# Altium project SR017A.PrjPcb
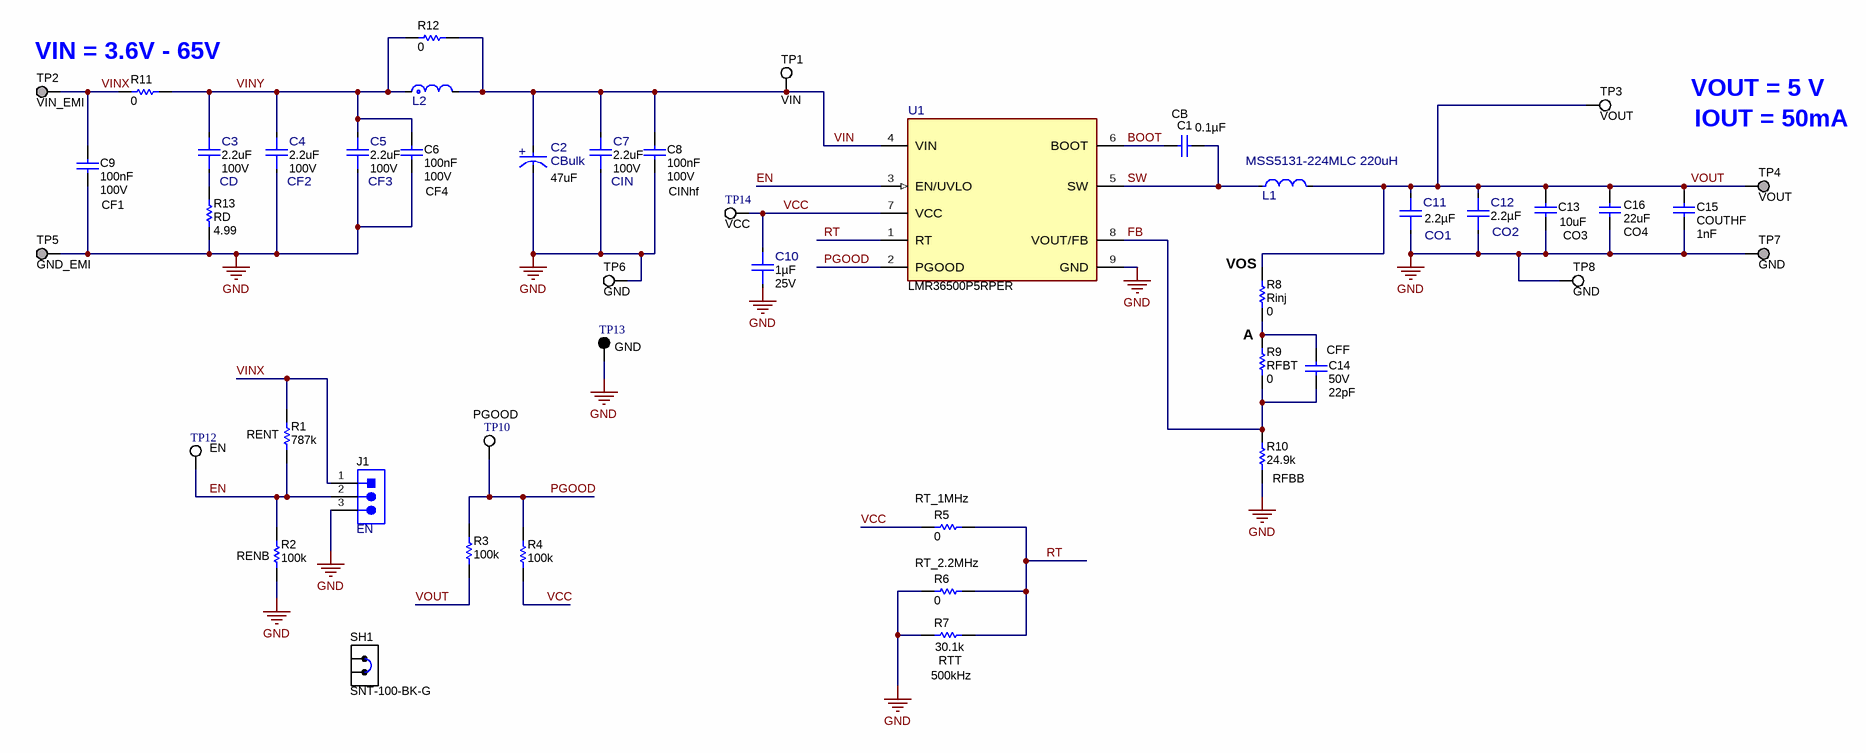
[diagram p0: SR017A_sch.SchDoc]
CopyrightYear: 2023; EVM_orderable: LMR36500EVM; PCB_Layout: FJD; PCB_Rev: A1; PRJ_Customer: Public Release; PRJ_Engineer: FJD; PRJ_Number: SR017; PRJ_Title: LMR36500EVM; SCH_Rev: A; TechSupport: http://www.ti.com/support; TID: N/A
2 sheets, 53 parts. Net scope: global (net labels, ports and power ports of the same name join across sheets).
Board file: SR017A_PCB.PcbDoc
Sheets:
  SR017A_sch.SchDoc
  SR017A_Hardware.SchDoc

## Sheet SR017A_sch.SchDoc
size 431 x 279 mm; Date: Not shown in title block; ApprovedBy: Not shown in title block; CheckedBy: Not shown in title block; Author: Not shown in title block; CompanyName: Not shown in title block; Engineer: Not shown in title block; Organization: Not shown in title block; Address1: Not shown in title block; Address2: Not shown in title block; Address3: Not shown in title block; Address4: Not shown in title block; DocumentNumber: 1; Revision: Use project parameter SCH_Rev; SheetNumber: 1; SheetTotal: 2; PageSetup: Record=PageOptions¦CenterHorizontal=True¦CenterVertical=True¦PrintScale=1.00¦XCorrection=1.00¦YCorrection=1.00¦PrintKind=0¦BorderSize=5000000¦LeftOffset=0¦BottomOffset=0¦Orientation=2¦PaperLength=1000¦PaperWidth=1000¦Scale=100¦PaperSource=15¦PrintQuality=600¦MediaType=1¦DitherType=10¦PaperKind=Letter¦PrintScaleMode=1

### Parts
C1  CB  ValueDisplayed: 0.1µF  [0402L]
C2  CBulk  ValueDisplayed: 47uF  [FP-476SML100M_RADIAL-IPC_C]
C3  CD  ValueDisplayed: 2.2uF  VDC_V: 100V  [FP-CL31Y225KCHVPNE_1206-MFG]
C4  CF2  ValueDisplayed: 2.2uF  VDC_V: 100V  [FP-CL31Y225KCHVPNE_1206-MFG]
C5  CF3  ValueDisplayed: 2.2uF  VDC_V: 100V  [FP-CL31Y225KCHVPNE_1206-MFG]
C6  CF4  Cap_F: 100nF  VDC_V: 100V  [0603L]
C7  CIN  ValueDisplayed: 2.2uF  VDC_V: 100V  [FP-CL31Y225KCHVPNE_1206-MFG]
C8  CINhf  Cap_F: 100nF  VDC_V: 100V  [0603L]
C9  CF1  Cap_F: 100nF  VDC_V: 100V  [0603L]
C10  Cap_F: 1µF  VDC_V: 25V  [FP-C1608X7R1E105K080AE_0603-MFG]  (hidden comment: CVCC)
C11  CO1  Cap_F: 2.2µF  [FP-GRM21BR71E225KE11L_0805-MFG]
C12  CO2  Cap_F: 2.2µF  [FP-GRM21BR71E225KE11L_0805-MFG]
C13  CO3  ValueDisplayed: 10uF  [1210_280]
C14  CFF  VDC_V: 50V  ValueDisplayed: 22pF  [0603L]
C15  COUTHF  Cap_F: 1nF  [0603L]
C16  CO4  ValueDisplayed: 22uF  [1210_270L]
J1  EN  [TSW-103-07-G-S]
L1  MSS5131-224MLC 220uH  [FP-MSS5131-224MLC_SMT2_5MM1_5MM1-MFG]
L2  XFL2010-102MEC  [FP-XFL2010-102MEC_SMT2_1MM9_2MM0-MFG]  (value not drawn)
R1  RENT  ValueDisplayed: 787k  [0603L]
R2  RENB  ValueDisplayed: 100k  [0603L]
R3  ValueDisplayed: 100k  [0603L]  (hidden comment: RPU1)
R4  ValueDisplayed: 100k  [0603L]  (hidden comment: RPU2)
R5  RT_1MHz  ValueDisplayed: 0  [0603L]
R6  RT_2.2MHz  ValueDisplayed: 0  [0603L]
R7  RTT  ValueDisplayed: 30.1k  [0603L]
R8  Rinj  ValueDisplayed: 0  [0603L]
R9  RFBT  ValueDisplayed: 0  [0603L]
R10  RFBB  ValueDisplayed: 24.9k  [0603L]
R11  ValueDisplayed: 0  [5108]  (hidden comment: RFILTJ)
R12  ValueDisplayed: 0  [5108]  (hidden comment: RSHUNT)
R13  RD  ValueDisplayed: 4.99  [0603L]
SH1  SNT-100-BK-G  [SNT-100-BK-G]
TP1  VIN  [Testpoint_Keystone_Miniature]
TP2  VIN_EMI  [Keystone1502-2]
TP3  VOUT  [Testpoint_Keystone_Miniature]
TP4  VOUT  [Keystone1502-2]
TP5  GND_EMI  [Keystone1502-2]
TP6  GND  [Testpoint_Keystone_Miniature]
TP7  GND  [Keystone1502-2]
TP8  GND  [Testpoint_Keystone_Miniature]
TP10  PGOOD  [Keystone5012]
TP12  EN  [Keystone5012]
TP13  GND  [Keystone5011]
TP14  VCC  [Keystone5012]
U1  LMR36500P5RPER  [RPE0009B-MFG]

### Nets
GND: C2.1(CATHODE) C4.1 C5.1 C6.2 C7.1 C8.2 C9.2 C10.1 C11.1 C12.1 C13.2 C15.1 C16.2 J1.3 R2.1 R6.1 R7.1 R10.1 R13.1 TP5.1 TP6.1 TP7.1 TP8.1 TP13.1 U1.9(GND)
BOOT: C1.2 U1.6(BOOT)
EN: J1.2 R1.1 R2.2 TP12.1 U1.3(EN/UVLO)
FB: C14.2 R9.1 R10.2 U1.8(VOUT/FB)
PGOOD: R3.2 R4.2 TP10.1 U1.2(PGOOD)
RT: R5.2 R6.2 R7.2 U1.1(RT)
SW: C1.1 L1.1 U1.5(SW)
VCC: C10.2 R4.1 R5.1 TP14.1 U1.7(VCC)
VIN: C2.2(ANODE) C7.2 C8.1 L2.2 R12.2 TP1.1 U1.4(VIN)
VINX: C9.1 J1.1 R1.2 R11.1 TP2.1
VINY: C3.2 C4.2 C5.2 C6.1 L2.1 R11.2 R12.1
VOUT: C11.2 C12.2 C13.1 C15.2 C16.1 L1.2 R3.1 R8.2 TP3.1 TP4.1
NetC3_1: C3.1 R13.2
NetC14_1: C14.1 R8.1 R9.2

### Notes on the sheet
- VIN = 3.6V - 65V
- VOUT = 5 V
- IOUT = 50mA
- (near R8) VOS
- (near R9) A
- (near R7) 500kHz

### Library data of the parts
C1 = CMP-0080610-1: CAP, CERM, 0.1 µF, 25 V,+/- 10%, X7R, AEC-Q200 Grade 1, 0402; Manufacturer: TDK; PartNumber: CGA2B3X7R1E104K050BB; TaMin_C: -55°C; Polarized: N; SizeAreaWB_mm2: 3; U/M: EA; Value: 0.1uF; TaMax_C: 125°C; SizeZ_mm: 0.6; SizeX_mm: 1; SizeY_mm: 0.5; Cap_Case: 0402; Value2: 25V; AEC Qualified: Y; Cap_F: 100nF; AEC Category: Q200
C2 = CMP-0095711-1: 47 µF 100 V Aluminum Electrolytic Capacitors Radial, Can - SMD 3.5274Ohm @ 120Hz 2000 Hrs @ 85°C; Part Number: 476SML100M; Manufacturer: Cornell Dubilier; Cap_F: 47µF; Value: 47µF; Life: 2000Hours; IRMS_A: 130mA; Dissipation Factor: 10%; AEC Qualified: No; SizeZ_mm: 11.3mm; VDC_V: 100V; Leakage Current: 47uA; Esr: 3.5274; Tolerance_%: 20%
C3-C5 C7 = CMP-0001547-1: Cap Ceramic 2.2uF 100V X7S 10% SMD 1206 125°C Emboss T/R; Manufacturer: Samsung; PartNumber: CL31Y225KCHVPNE; AEC Grade: Grade 1; AEC Qualified: Yes; Cap_F: 2.2µF; SizeZ_mm: 1.8mm; TempCo: 22%; Value: 2.2µF
C6 C8 C9 = CMP-0007469-4: CAP, CERM, 0.1 uF, 100 V, +/- 10%, X7R, 0603; Manufacturer: MuRata; PartNumber: GRM188R72A104KA35D; TaMin_C: -55°C; Polarized: N; SizeAreaWB_mm2: 4.68; Value1: Unknown; U/M: EA; Value: 0.1uF; TaMax_C: 125°C; SizeZ_mm: 1; SizeX_mm: 1.6; SizeY_mm: 0.8; Cap_Case: 0603; SizeArea_mm2: 1.28; AEC Category: Q200
C10 = CMP-0116394-1: C Series 0603 1 uF 25 V ±10 %Tolerance X7R SMT Multilayer Ceramic Capacitor; Manufacturer: TDK; PartNumber: C1608X7R1E105K080AE; AEC Qualified: No; SizeZ_mm: 0.95mm; TempCo: 15%; Tolerance_%: 10%; ValueDisplayed: 1uF; Value: 1µF
C11 C12 = CMP-0001537-1: Chip Multilayer Ceramic Capacitors for General Purpose, 0805, 2.2uF, X7R, 15%, 10%, 25V; Manufacturer: Murata; PartNumber: GRM21BR71E225KE11L; AEC Qualified: No; SizeZ_mm: 1.4mm; Value: 2.2µF
C13 = CMP-0009078-1: CAP, CERM, 10 uF, 25 V, +/- 10%, X7R, 1210; Manufacturer: Kemet; PartNumber: C1210C106K3RACTU; TaMin_C: -55°C; Polarized: N; SizeAreaWB_mm2: 14.7; Value1: Unknown; U/M: EA; Value: 10uF; TaMax_C: 125°C; SizeZ_mm: 2.8; SizeX_mm: 3.2; SizeY_mm: 2.5; Cap_Case: 1210; Value2: 25V; SizeArea_mm2: 8; Cap_F: 10µF; AEC Category: Q200
C14 = CMP-0006775-2: CAP, CERM, 22 pF, 50 V, +/- 5%, C0G/NP0, 0603; Manufacturer: AVX; PartNumber: 06035A220JAT2A; TaMin_C: -55°C; ESR_ohm: 0.259; Polarized: N; SizeAreaWB_mm2: 4.68; Value1: 0.259 ohm; U/M: EA; Value: 22pF; TaMax_C: 125°C; SizeZ_mm: 1; SizeX_mm: 1.6; SizeY_mm: 0.8; Cap_Case: 0603; SizeArea_mm2: 1.28; AEC Category: Q200
C15 = CMP-0007467-4: CAP, CERM, 1000 pF, 100 V, +/- 10%, X7R, 0603; Manufacturer: MuRata; PartNumber: GRM188R72A102KA01D; TaMin_C: -55°C; Polarized: N; SizeAreaWB_mm2: 4.68; Value1: Unknown; U/M: EA; Value: 1000pF; TaMax_C: 125°C; SizeZ_mm: 1; SizeX_mm: 1.6; SizeY_mm: 0.8; Cap_Case: 0603; Value2: 100V; SizeArea_mm2: 1.28; CompType: Capacitor; AEC Category: Q200
C16 = CMP-0009224-2: CAP, CERM, 22 uF, 25 V, +/- 10%, X7R, 1210; Manufacturer: MuRata; PartNumber: GRM32ER71E226KE15L; TaMin_C: -55°C; Polarized: N; SizeAreaWB_mm2: 14.7; Value1: Unknown; U/M: EA; Value: 22uF; TaMax_C: 125°C; SizeZ_mm: 2.7; SizeX_mm: 3.2; SizeY_mm: 2.5; Cap_Case: 1210; Value2: 25V; SizeArea_mm2: 8; Cap_F: 22µF; AEC Category: Q200
J1 = CMP-0075407-2: Header, 100mil, 3x1, Gold, TH; Manufacturer: Samtec; Pitch_mm: 2.54; Cert_VDE: N; Gender: Male; Cert_CSA: Y; Voltage_V: 550V; Green_REACh: Passed; Current_A: 6.3A; Green_Lifecycle: Active; Row_Count: 1
L1 = CMP-0001415-1: Power Inductors - SMD 220uH Shld 20% 0.5A 1.1ohms AEC-Q200; Manufacturer: Coilcraft; AEC Grade: Grade 3; AEC Qualified: Yes; DCR_ohm: 1.1; Ind_H: 220µH; Isat: 0.18A; Material: Ferrite; SizeZ_mm: 3.1mm; Self Resonant Frequency: 8MHz; Shrouded: true; TaMax_C: +85°C; TaMin_C: -40°C; Test Frequency: 100kHz
L2 = CMP-0001495-1: 1 µH Shielded Inductor 1.3 A 83mOhm Max Nonstandard; Manufacturer: Coilcraft; AEC Grade: Grade 1; AEC Qualified: Yes; DCR_ohm: 0.083; Ind_H: 1µH; Irms: 1.8A; Isat: 0.95A; Material: Composite; SizeZ_mm: 1mm; Value: 1uH; Self Resonant Frequency: 130MHz; Shrouded: true; TaMax_C: +125°C; TaMin_C: -40°C; Test Frequency: 1MHz; Tolerance_%: 20%
R1 = CMP-0023273-4: RES, 787 k, 1%, 0.1 W, 0603; Manufacturer: Yageo; PartNumber: RC0603FR-07787KL; Power_W: 100mW; TempCo: 100 ppm/C; Value: 787k; EIA_Code: E96; SizeX_mm: 1.6; SizeY_mm: 0.8; SizeZ_mm: 1; Value2: 0.1W; SizeArea_mm2: 1.28; AEC Qualified: N; VDC_V: 75V; AEC Category: Q200; SizeAreaWB_mm2: 4.68
R2-R4 = CMP-0022735-5: RES, 100 k, 1%, 0.1 W, 0603; Manufacturer: Yageo; PartNumber: RC0603FR-07100KL; Power_W: 100mW; TempCo: 100 ppm/C; Value: 100k; EIA_Code: E96; SizeX_mm: 1.6; SizeY_mm: 0.8; SizeZ_mm: 1; Value2: 0.1W; SizeArea_mm2: 1.28; AEC Qualified: N; VDC_V: 75V; AEC Category: Q200; SizeAreaWB_mm2: 4.68
R5 R6 R8 R9 = CMP-0023343-2: RES, 0, 1%, 0.1 W, AEC-Q200 Grade 0, 0603; Manufacturer: Stackpole Electronics Inc; PartNumber: RMCF0603ZT0R00; Power_W: 100mW; TempCo: ppm/C; U/M: EA; Value: 0; SizeX_mm: 1.6; SizeY_mm: 0.8; SizeZ_mm: 1; Value2: 0.1W; SizeArea_mm2: 1.28; AEC Qualified: Y; AEC Category: Q200
R7 = CMP-0023018-5: RES, 30.1 k, 1%, 0.1 W, 0603; Manufacturer: Yageo; PartNumber: RC0603FR-0730K1L; Power_W: 100mW; TempCo: 100 ppm/C; Value_Code: 30k1; Value: 30.1k; EIA_Code: E96; SizeX_mm: 1.6; SizeY_mm: 0.8; SizeZ_mm: 1; Value2: 0.1W; SizeArea_mm2: 1.28; AEC Qualified: N; VDC_V: 75V; AEC Category: Q200; SizeAreaWB_mm2: 4.68
R10 = CMP-0022237-1: RES, 24.9 k, 1%, 0.1 W, 0603; Manufacturer: Vishay-Dale; PartNumber: CRCW060324K9FKEA; Power_W: 100mW; TempCo: 100 ppm/C; Value_Code: 24k9; U/M: EA; Value: 24.9k; EIA_Code: E96; SizeX_mm: 1.6; SizeY_mm: 0.8; SizeZ_mm: 1; Value2: 0.1W; SizeArea_mm2: 1.28; VDC_V: 75V; AEC Category: Q200
R11 R12 = CMP-0016567-2: RES, 0, 1%, 0.5 W, 1206; Manufacturer: Keystone; Power_W: 500mW; TempCo: ppm/C; U/M: EA; Value: 0; SizeX_mm: 3.05; SizeY_mm: 1.7; SizeZ_mm: 0.84; Value2: 0.5W; SizeArea_mm2: 5.185; CompType: Resistor; AEC Qualified: N; AEC Category: Q200
R13 = CMP-0022478-4: RES, 4.99, 1%, 0.1 W, AEC-Q200 Grade 0, 0603; Manufacturer: Vishay-Dale; PartNumber: CRCW06034R99FKEA; Power_W: 100mW; TempCo: 100 ppm/C; Value_Code: 4R99; Value: 4.99; EIA_Code: E96; SizeX_mm: 1.6; SizeY_mm: 0.8; SizeZ_mm: 1; Value2: 0.1W; SizeArea_mm2: 1.28; CompType: Resistor; AEC Qualified: Y; VDC_V: 75V; AEC Category: Q200; AEC Grade: 0
SH1 = CMP-0003623-3: Shunt, 100mil, Gold plated, Black; Alternate PartNumber: 969102-0000-DA; Manufacturer: Samtec; Alternate Manufacturer: 3M; Value: 1x2
TP1 TP3 TP6 TP8 = CMP-0055152-1: Test Point, Miniature, SMT; Manufacturer: Keystone; PartNumber: 5015; CNHeader: FALSE; Green_Lifecycle: Active; Green_REACh: Passed; CT: TRUE
TP2 TP4 TP5 TP7 = CMP-0055113-1: Terminal, Turret, TH, Double; Manufacturer: Keystone; PartNumber: 1502-2; CT: FALSE; Green_REACh: Passed; CompType: Turret Terminal; Green_Lifecycle: Active
TP10 TP12 TP14 = CMP-0055149-1: Test Point, Multipurpose, White, TH; Manufacturer: Keystone; CNHeader: FALSE; Green_Lifecycle: Active; Green_REACh: Passed; ContactFinish: Silver; CT: TRUE
TP13 = CMP-0055148-1: Test Point, Multipurpose, Black, TH; Manufacturer: Keystone; CNHeader: FALSE; Green_Lifecycle: Active; Green_REACh: Passed; ContactFinish: Silver; CT: TRUE
U1 = CMP-0001448-1: 3-V to 65-V, 50-mA Wide VIN Synchronous Buck Converter Optimized for Size and Light Load Efficiency; Manufacturer: Texas Instruments; SizeZ_mm: 1mm; AEC Qualified: No; Max Supply Voltage: 65V; Min Supply Voltage: 3V; Nominal Supply Current: 4uA; Number Of Outputs: 1; Standoff Height: 0mm; Switching Frequency: 200-2200kHz; TJmax_C: +150°C

## Sheet SR017A_Hardware.SchDoc
size 431 x 279 mm; Date: Not shown in title block; ApprovedBy: Not shown in title block; CheckedBy: Not shown in title block; Author: Not shown in title block; CompanyName: Not shown in title block; Engineer: Not shown in title block; Organization: Not shown in title block; Address1: Not shown in title block; Address2: Not shown in title block; Address3: Not shown in title block; Address4: Not shown in title block; DocumentNumber: 3; Revision: Use project parameter SCH_Rev; SheetNumber: 3; SheetTotal: 3; PageSetup: Record=PageOptions¦CenterHorizontal=True¦CenterVertical=True¦PrintScale=1.00¦XCorrection=1.00¦YCorrection=1.00¦PrintKind=0¦BorderSize=5000000¦LeftOffset=0¦BottomOffset=0¦Orientation=2¦PaperLength=1000¦PaperWidth=1000¦Scale=100¦PaperSource=15¦PrintQuality=600¦MediaType=1¦DitherType=10¦PaperKind=Letter¦PrintScaleMode=1
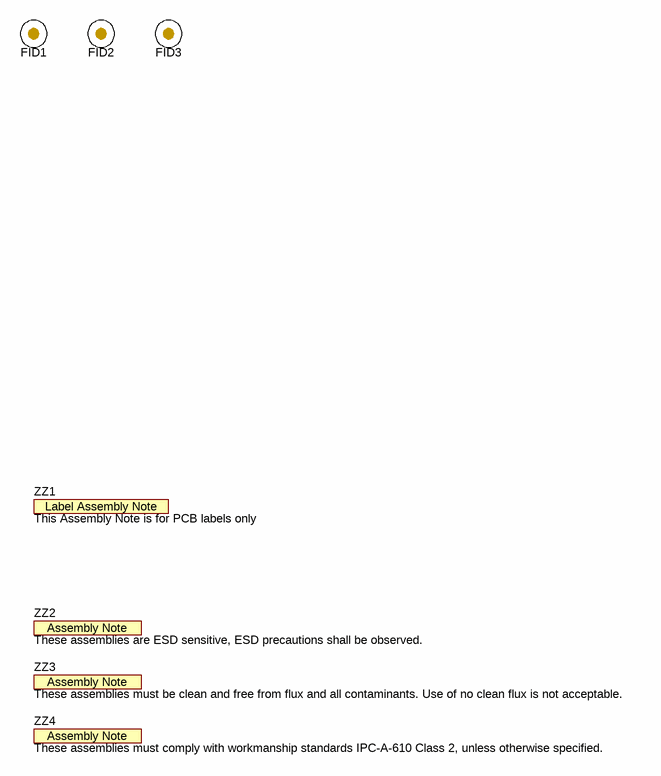
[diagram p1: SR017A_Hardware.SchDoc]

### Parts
FID1  Fiducial  [Fiducial10-20]  (value not drawn)
FID2  Fiducial  [Fiducial10-20]  (value not drawn)
FID3  Fiducial  [Fiducial10-20]  (value not drawn)
ZZ1  This Assembly Note is for PCB labels only  [AssemblyNoteLabel]  (no BOM)
ZZ2  These assemblies are ESD sensitive, ESD precautions shall be observed.  [AssemblyNote]  (no BOM)
ZZ3  These assemblies must be clean and free from flux and all contaminants. Use of no clean flux is not acceptable.  [AssemblyNote]  (no BOM)
ZZ4  These assemblies must comply with workmanship standards IPC-A-610 Class 2, unless otherwise specified.  [AssemblyNote]  (no BOM)

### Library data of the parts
FID1-FID3 = CMP-0077181-1: Fiducial mark.  There is nothing to buy or mount.
ZZ1 = CMP-0003616-3
ZZ2 = CMP-0077236-1
ZZ3 = CMP-0077237-1
ZZ4 = CMP-0077238-1

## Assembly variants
001: not fitted C3 C4 C5 C6 C9 C13 C14 C16 FID1 FID2 FID3 L2 R1 R2 R3 R6 R7 R10 R13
